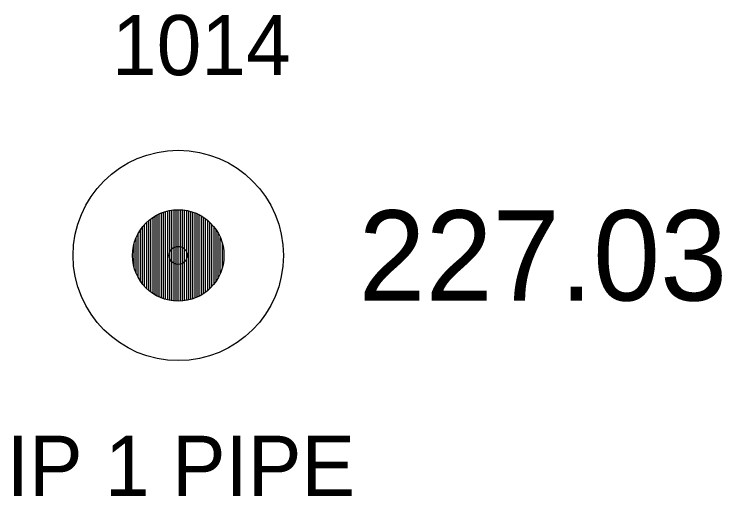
# Model space of a CAD drawing. Extents: x 1961231 to 1962574, y 799865 to 801120.
# Drawn here: x 1962136.96 to 1962148.74, y 799865.43 to 799873.44 of the extents above; entities that cross this region are included whole.
import ezdxf

# ---------------------------------------------------------------- set-up
doc = ezdxf.new("R2010")
doc.units = 0
for name, color, linetype in [('RD_EX_DV_Prop_txCode', 7, 'Continuous'), ('RD_EX_DV_PropPin', 7, 'Continuous'), ('RD_EX_TX_DV_Prop_ELEV', 7, 'Continuous'), ('RD_SMD_Locator', 7, 'Continuous')]:
    doc.layers.add(name, color=color, linetype=linetype)

msp = doc.modelspace()

# ---------------------------------------------------------------- linework, layer by layer
at = {"layer": 'RD_EX_DV_PropPin'}
for p, q in [((1962139.415, 799868.722), (1962139.415, 799870.137)), ((1962139.45, 799868.709), (1962139.45, 799870.15)), ((1962139.485, 799868.698), (1962139.485, 799870.161)), ((1962139.52, 799868.688), (1962139.52, 799870.17)), ((1962139.555, 799868.681), (1962139.555, 799870.177)), ((1962139.59, 799868.675), (1962139.59, 799870.183)), ((1962139.625, 799868.671), (1962139.625, 799870.187)), ((1962139.66, 799868.669), (1962139.66, 799870.189)), ((1962139.695, 799868.668), (1962139.695, 799870.19)), ((1962139.73, 799868.669), (1962139.73, 799870.189)), ((1962139.765, 799868.671), (1962139.765, 799870.187)), ((1962139.8, 799868.675), (1962139.8, 799870.183)), ((1962139.835, 799868.681), (1962139.835, 799870.177)), ((1962139.87, 799868.688), (1962139.87, 799870.17)), ((1962139.905, 799868.698), (1962139.905, 799870.161)), ((1962139.94, 799868.709), (1962139.94, 799870.15)), ((1962139.975, 799868.722), (1962139.975, 799870.137)), ((1962139.24, 799868.819), (1962139.24, 799870.039)), ((1962139.275, 799868.795), (1962139.275, 799870.064)), ((1962139.31, 799868.773), (1962139.31, 799870.085)), ((1962139.345, 799868.753), (1962139.345, 799870.105)), ((1962139.38, 799868.736), (1962139.38, 799870.122)), ((1962140.01, 799868.736), (1962140.01, 799870.122)), ((1962140.045, 799868.753), (1962140.045, 799870.105)), ((1962140.08, 799868.773), (1962140.08, 799870.085)), ((1962140.115, 799868.795), (1962140.115, 799870.064)), ((1962140.15, 799868.819), (1962140.15, 799870.039)), ((1962139.1, 799868.955), (1962139.1, 799869.903)), ((1962139.135, 799868.914), (1962139.135, 799869.944)), ((1962139.17, 799868.878), (1962139.17, 799869.98)), ((1962139.205, 799868.847), (1962139.205, 799870.011)), ((1962140.185, 799868.847), (1962140.185, 799870.011)), ((1962140.22, 799868.878), (1962140.22, 799869.98)), ((1962140.255, 799868.914), (1962140.255, 799869.944)), ((1962140.29, 799868.955), (1962140.29, 799869.903)), ((1962139.03, 799869.06), (1962139.03, 799869.799)), ((1962139.065, 799869.003), (1962139.065, 799869.856)), ((1962140.325, 799869.003), (1962140.325, 799869.856)), ((1962140.36, 799869.06), (1962140.36, 799869.799)), ((1962138.994, 799869.131), (1962138.994, 799869.727)), ((1962140.395, 799869.131), (1962140.395, 799869.727)), ((1962138.959, 799869.233), (1962138.959, 799869.625)), ((1962140.43, 799869.233), (1962140.43, 799869.625))]:
    msp.add_line(p, q, dxfattribs=at)
for radius in [1.75, 0.761]:
    msp.add_circle((1962139.695, 799869.429), radius, dxfattribs=at)
at = {"layer": 'RD_SMD_Locator'}
msp.add_circle((1962139.695, 799869.429), 0.15, dxfattribs=at)

# ---------------------------------------------------------------- texts
at = {"layer": 'RD_EX_DV_Prop_txCode'}
for s, p in [('1014', (1962138.592, 799872.429)), ('IP 1 PIPE', (1962136.84, 799865.429))]:
    msp.add_text(s, height=1, dxfattribs=at).set_placement(p)
at = {"layer": 'RD_EX_TX_DV_Prop_ELEV'}
msp.add_text('227.03', height=1.5, dxfattribs=at).set_placement((1962142.695, 799868.679))

doc.saveas('drawing.dxf')
